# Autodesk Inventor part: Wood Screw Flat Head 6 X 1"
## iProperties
Shininess: 28.0
Length Units: 11272
Angle Units: 11279
Time Units: 11290
Mass Units: 11286
Length Display Precision: 4
Angle Display Precision: 2
Compacted: True
Category: Fasteners
Created: 2005-10
Part Number: Wood Screw Flat Head 6 X 1"
Material: Steel, Carbon
Description: Wood Screw Flat Head
Document SubType Name: Modeling
Designer: JDP
Density: 7.84
Volumn: 0.0334175022831377
Area: 0.7931629180511741
PropertySet Name: Model Information
Control State: 0
Master: False
Checked Out: False
SUB-ASSEMBLY: HARDWARE
MATERIAL NAME: Wood Screw Flat Head 6 X 1"
MATERIAL TYPE: Other Item
Author: Joshua Petitt
Comments: A basic wood screw.  NO GUARANTEES ARE MADE ABOUT THE ACCURACY OF THE PART MODEL OR TABLE.  USE AT YOUR OWN RISK.
Revision Number: A
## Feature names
1. Revolution1
2. slot [Extrusion]
3. Circular Pattern1
4. Coil1
5. Coil2
